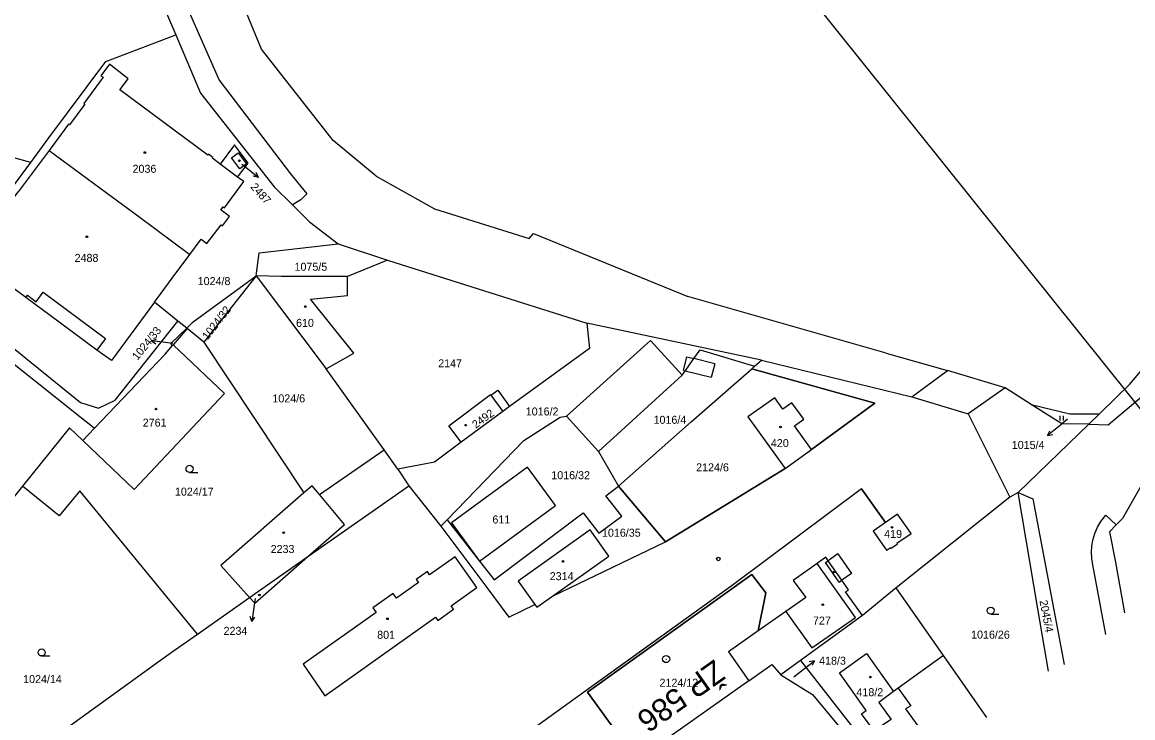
# Model space of a CAD drawing. Extents: x -793666 to -785424, y -1118958 to -1108761.
# Drawn here: x -792219.4 to -791983.5, y -1109753.4 to -1109605.6 of the extents above; entities that cross this region are included whole.
import ezdxf

# ---------------------------------------------------------------- set-up
doc = ezdxf.new("R2010")
doc.units = 0
for name, color, linetype in [('1', 7, 'Continuous'), ('1_2000 - úřady', 7, 'Continuous'), ('Hranice parcel', 7, 'Continuous'), ('Parcelní čísla', 7, 'Continuous'), ('Pop  PČ popisy', 7, 'Continuous'), ('Vnitřní kresba', 7, 'Continuous'), ('Vrstva 44', 7, 'Continuous'), ('Vrstva 53', 7, 'Continuous'), ('Vrstva 63', 7, 'Continuous'), ('Značky budov', 7, 'Continuous'), ('Značky kultur', 7, 'Continuous')]:
    doc.layers.add(name, color=color, linetype=linetype)

msp = doc.modelspace()

# ---------------------------------------------------------------- linework, layer by layer
at = {"layer": '1'}
for p, q in [((-792041.12, -1109704.75), (-792068.33, -1109725.02)), ((-792041.12, -1109704.75), (-792036.03, -1109711.9)), ((-792068.33, -1109725.02), (-792087.87, -1109739.13)), ((-792087.87, -1109739.13), (-792101.91, -1109749.26))]:
    msp.add_line(p, q, dxfattribs=at)
msp.add_lwpolyline([(-792036.03, -1109711.9), (-792041.12, -1109704.75), (-792068.33, -1109725.02), (-792101.91, -1109749.26), (-792182.09, -1109807.15)], dxfattribs=at)
msp.add_circle((-792071.53, -1109719.62), 0.375, dxfattribs=at)
at = {"layer": '1_2000 - úřady'}
msp.add_lwpolyline([(-791938.08, -1109742.36), (-792598.01, -1110271.46), (-792786.15, -1110036.8), (-792126.22, -1109507.7)], close=True, dxfattribs=at)
at = {"layer": 'Hranice parcel'}
for p, q in [((-792144.2, -1109638.25), (-792153.37, -1109630.69)), ((-792213.73, -1109632.8), (-792220.3, -1109641.62)), ((-792221.51, -1109640.65), (-792217.57, -1109635.36)), ((-792173.66, -1109638.47), (-792177.37, -1109635.72)), ((-792110.82, -1109650.45), (-792078.02, -1109663.86)), ((-792152.29, -1109652.69), (-792141.79, -1109656.16)), ((-792141.79, -1109656.16), (-792150.31, -1109659.57)), ((-792141.79, -1109656.16), (-792099.45, -1109669.52)), ((-792169.71, -1109659.46), (-792180.81, -1109673.54)), ((-792169.71, -1109659.46), (-792154.82, -1109679.25)), ((-792186.33, -1109669.08), (-792191.31, -1109665.06)), ((-792035.89, -1109675.87), (-792078.02, -1109663.86)), ((-792184.48, -1109670.58), (-792186.33, -1109669.08)), ((-792062.33, -1109677.36), (-792099.45, -1109669.52)), ((-792184.35, -1109670.68), (-792187.37, -1109674.13)), ((-792184.48, -1109670.58), (-792184.35, -1109670.68)), ((-792180.81, -1109673.54), (-792184.35, -1109670.68)), ((-792187.37, -1109674.13), (-792187.46, -1109674.24)), ((-792180.81, -1109673.54), (-792159.56, -1109705.6)), ((-792035.89, -1109675.87), (-792022.82, -1109679.59)), ((-792064.43, -1109679.2), (-792063.84, -1109678.68)), ((-792063.84, -1109678.68), (-792062.33, -1109677.36)), ((-792010.6, -1109683.28), (-792022.82, -1109679.59)), ((-792005.04, -1109686.79), (-792010.6, -1109683.28)), ((-791987, -1109685.32), (-791984.15, -1109682.54)), ((-791987, -1109685.32), (-791990.54, -1109688.77)), ((-792117.28, -1109688.25), (-792126.16, -1109694.83)), ((-791990.54, -1109688.77), (-791992.82, -1109691)), ((-792007.85, -1109705.47), (-791992.82, -1109691)), ((-792206.56, -1109694.48), (-792204.05, -1109691.84)), ((-791974.78, -1109691.82), (-791985.69, -1109711.05)), ((-792057.33, -1109700.37), (-792051.73, -1109696.36)), ((-792139.61, -1109700.53), (-792137.25, -1109704.07)), ((-792057.33, -1109700.37), (-792082.74, -1109715.97)), ((-792219.35, -1109704.16), (-792293.96, -1109796.98)), ((-792158.73, -1109719.12), (-792137.25, -1109704.07)), ((-792137.25, -1109704.07), (-792130.48, -1109712.65)), ((-792082.74, -1109715.97), (-792092.71, -1109704.13)), ((-792007.85, -1109705.47), (-792009.6, -1109706.46)), ((-792009.6, -1109706.46), (-792033.77, -1109725.73)), ((-792130.48, -1109712.65), (-792129.14, -1109711.27)), ((-791989.17, -1109710.28), (-791986.99, -1109712.39)), ((-791985.69, -1109711.05), (-791986.99, -1109712.39)), ((-792106.76, -1109727.49), (-792082.74, -1109715.97)), ((-792171.12, -1109727.8), (-792158.73, -1109719.12)), ((-791989.17, -1109735.63), (-791991.98, -1109720.83)), ((-792033.77, -1109725.73), (-792040.87, -1109731.66)), ((-792023.66, -1109740.13), (-792033.77, -1109725.73)), ((-792182.21, -1109735.57), (-792171.12, -1109727.8)), ((-792040.87, -1109731.66), (-792054.08, -1109741.21)), ((-792014.46, -1109753.3), (-792023.66, -1109740.13)), ((-792054.08, -1109741.21), (-792058.28, -1109744.24)), ((-792065.02, -1109745.49), (-792088.89, -1109762.3))]:
    msp.add_line(p, q, dxfattribs=at)
for points in [[(-792216.04, -1109494.77), (-792211.63, -1109526.92), (-792206.15, -1109541.38), (-792188.4, -1109593.25), (-792177.58, -1109617.9), (-792162.42, -1109637.81), (-792158.94, -1109642.01), (-792160.24, -1109643.3), (-792162, -1109644.38)], [(-792153.37, -1109630.69), (-792168.6, -1109611.32), (-792177.54, -1109589.6), (-792190.39, -1109550.74), (-792201.74, -1109515.1), (-792204.07, -1109507.78)], [(-792207.68, -1109547.79), (-792203.58, -1109560.85), (-792192.49, -1109594.88), (-792186.8, -1109608.25)], [(-792217.57, -1109635.36), (-792213.74, -1109630.12), (-792201.64, -1109613.93), (-792186.8, -1109608.25)], [(-792186.8, -1109608.25), (-792181.52, -1109620.67), (-792165.87, -1109640.54), (-792162, -1109644.38)], [(-792177.37, -1109635.72), (-792179.03, -1109634.49), (-792178.9, -1109634.32), (-792179.84, -1109633.63), (-792179.96, -1109633.8), (-792198.68, -1109619.95), (-792196.88, -1109617.57), (-792200.88, -1109614.49), (-792202.69, -1109616.98), (-792202.24, -1109617.28), (-792206.36, -1109622.83), (-792206.12, -1109623.01), (-792209.36, -1109627.39), (-792209.6, -1109627.21), (-792213.73, -1109632.8)], [(-792173.66, -1109638.47), (-792171.45, -1109635.49), (-792174.33, -1109631.62), (-792177.37, -1109635.72)], [(-791984.15, -1109682.54), (-791976.2, -1109673.16), (-791951.58, -1109631.36)], [(-792217.57, -1109635.36), (-792223.23, -1109633.79), (-792229.23, -1109634.41)], [(-792213.73, -1109632.8), (-792201.58, -1109641.77), (-792194.65, -1109646.88), (-792183.83, -1109654.9)], [(-792265.17, -1109639.25), (-792207.01, -1109686.37), (-792203.19, -1109687.6), (-792199.7, -1109685.86), (-792186.33, -1109669.08)], [(-792183.83, -1109654.9), (-792181.4, -1109651.65), (-792180.18, -1109652.56), (-792177.13, -1109648.66), (-792176.88, -1109648.85), (-792175.39, -1109646.84), (-792177.24, -1109645.47), (-792176.73, -1109644.79), (-792176.47, -1109644.98), (-792172.37, -1109639.42), (-792173.66, -1109638.47)], [(-792144.2, -1109638.25), (-792131.8, -1109645.19), (-792111.75, -1109651.55), (-792110.82, -1109650.45)], [(-792269.36, -1109639.81), (-792207.16, -1109689.36), (-792204.47, -1109691.5), (-792204.05, -1109691.84)], [(-792191.31, -1109665.06), (-792200.45, -1109677.48), (-792203.54, -1109675.23), (-792211.54, -1109669.29), (-792218.63, -1109664.04), (-792221.71, -1109661.79), (-792221.38, -1109661.32), (-792230.1, -1109654.77), (-792228.64, -1109652.81), (-792220.3, -1109641.62)], [(-792162, -1109644.38), (-792158.37, -1109647.98), (-792152.29, -1109652.69)], [(-792169.71, -1109659.46), (-792169.08, -1109654.55), (-792152.29, -1109652.69)], [(-792191.31, -1109665.06), (-792189.92, -1109663.17), (-792187.54, -1109659.95), (-792183.83, -1109654.9)], [(-792184.48, -1109670.58), (-792183.09, -1109669.26), (-792169.71, -1109659.46)], [(-792150.31, -1109659.57), (-792164.44, -1109659.59), (-792169.71, -1109659.46)], [(-792154.82, -1109679.25), (-792148.96, -1109675.87), (-792158.15, -1109664.45), (-792150.34, -1109663.66), (-792150.31, -1109659.57)], [(-792099.45, -1109669.52), (-792098.89, -1109674.87), (-792115.88, -1109687.23), (-792117.28, -1109688.25)], [(-792187.46, -1109674.24), (-792187.87, -1109673.81), (-792184.48, -1109670.58)], [(-792187.37, -1109674.13), (-792176.46, -1109684.49), (-792195.66, -1109704.89), (-792206.56, -1109694.48)], [(-792204.05, -1109691.84), (-792189.07, -1109676.08), (-792187.46, -1109674.24)], [(-792103.8, -1109689.27), (-792085.97, -1109673.17), (-792079.18, -1109680.58), (-792078.56, -1109679.69), (-792076.71, -1109677.05), (-792075.42, -1109675.2), (-792063.84, -1109678.68)], [(-792139.61, -1109700.53), (-792142.53, -1109696.46), (-792154.82, -1109679.25)], [(-792092.71, -1109704.13), (-792077.28, -1109690.45), (-792064.43, -1109679.2)], [(-792064.43, -1109679.2), (-792038.26, -1109686.52), (-792051.73, -1109696.36)], [(-792062.33, -1109677.36), (-792030.44, -1109685.15), (-792018.46, -1109688.78), (-792009.6, -1109706.46)], [(-792126.16, -1109694.83), (-792128.78, -1109691.3), (-792119.95, -1109684.65), (-792119.83, -1109684.81), (-792117.28, -1109688.25)], [(-792051.73, -1109696.36), (-792055.31, -1109691.31), (-792053.36, -1109689.93), (-792055.88, -1109686.41), (-792057.81, -1109687.78), (-792059.53, -1109685.37), (-792065.26, -1109689.44), (-792057.33, -1109700.37)], [(-791992.82, -1109691), (-791998.55, -1109690.88), (-792005.04, -1109686.79)], [(-792005.04, -1109686.79), (-791996.82, -1109688.79), (-791990.54, -1109688.77)], [(-792129.14, -1109711.27), (-792112.82, -1109694.46), (-792105.12, -1109689.46), (-792103.8, -1109689.27)], [(-792103.8, -1109689.27), (-792096.98, -1109696.76), (-792092.71, -1109704.13)], [(-792206.56, -1109694.48), (-792209.4, -1109691.78), (-792219.35, -1109704.16)], [(-792126.16, -1109694.83), (-792131.81, -1109699.06), (-792139.61, -1109700.53)], [(-792106.12, -1109708.23), (-792112.07, -1109700.09), (-792128.21, -1109711.96), (-792122.26, -1109720.08), (-792106.12, -1109708.23)], [(-792182.21, -1109735.57), (-792185.42, -1109731.65), (-792207.17, -1109705.16), (-792211.55, -1109710.42), (-792219.35, -1109704.16)], [(-792158.73, -1109719.12), (-792150.95, -1109712.28), (-792156.26, -1109705.94), (-792157.82, -1109704.08), (-792159.56, -1109705.6)], [(-792129.14, -1109711.27), (-792122.26, -1109720.08), (-792119.15, -1109724.06), (-792100.25, -1109709.81), (-792096.91, -1109714.15), (-792092.06, -1109710.49), (-792095.42, -1109706.17), (-792092.71, -1109704.13)], [(-792007.85, -1109705.47), (-792004.71, -1109706.83), (-791998.08, -1109742.02)], [(-792001.39, -1109743.48), (-792003.64, -1109730.21), (-792007.85, -1109705.47)], [(-792159.56, -1109705.6), (-792177.21, -1109720.99), (-792171.12, -1109727.8)], [(-792038.61, -1109713.71), (-792035.77, -1109717.77), (-792034.88, -1109717.16), (-792034.78, -1109717.31), (-792033.49, -1109716.43), (-792033.6, -1109716.27), (-792030.57, -1109714.17), (-792033.44, -1109710.08), (-792038.61, -1109713.71)], [(-791991.98, -1109720.83), (-791992.2, -1109719.5), (-791992.26, -1109718.2), (-791992.18, -1109716.87), (-791991.97, -1109715.65), (-791991.56, -1109714.23), (-791990.95, -1109712.85), (-791990.23, -1109711.63), (-791989.17, -1109710.28)], [(-791986.99, -1109712.39), (-791988.4, -1109713.84), (-791987.24, -1109719.97), (-791985.22, -1109731.09)], [(-792130.48, -1109712.65), (-792120.92, -1109725.39), (-792116.05, -1109731.95), (-792110.51, -1109729.29)], [(-792106.76, -1109727.49), (-792094.78, -1109719), (-792098.73, -1109713.45), (-792114.05, -1109724.35), (-792110.51, -1109729.29)], [(-792171.12, -1109727.8), (-792170.01, -1109729.04), (-792158.73, -1109719.12)], [(-792139.92, -1109727.96), (-792140.61, -1109726.97), (-792144.91, -1109730.01), (-792144.21, -1109731), (-792159.76, -1109741.99), (-792155.1, -1109748.67), (-792131.63, -1109731.96), (-792131.14, -1109732.66), (-792127.76, -1109730.25), (-792128.26, -1109729.56), (-792122.8, -1109725.68), (-792127.44, -1109719.13), (-792132.86, -1109722.97), (-792133.35, -1109722.27), (-792135.73, -1109723.95), (-792135.23, -1109724.65), (-792139.92, -1109727.96)], [(-792040.87, -1109731.66), (-792044.51, -1109726.58), (-792043.88, -1109726.16), (-792045.28, -1109724.14), (-792048.16, -1109719.98), (-792048.66, -1109719.25), (-792050.55, -1109720.58), (-792055.65, -1109724.16), (-792052.97, -1109727.83), (-792057.17, -1109730.8), (-792063.04, -1109734.91)], [(-792088.89, -1109762.3), (-792099.3, -1109747.92), (-792064.44, -1109722.94), (-792061.45, -1109726.78), (-792063.04, -1109734.91)], [(-792110.51, -1109729.29), (-792110.1, -1109729.86), (-792106.76, -1109727.49)], [(-792226.53, -1109766.83), (-792215.1, -1109759.26), (-792190.07, -1109741.13), (-792187.8, -1109739.49), (-792182.21, -1109735.57)], [(-792063.04, -1109734.91), (-792069.34, -1109739.32), (-792065.02, -1109745.49)], [(-792023.66, -1109740.13), (-792033.34, -1109747.1), (-792034.31, -1109747.79), (-792037.43, -1109750.08), (-792034.83, -1109753.69), (-792037.49, -1109755.5), (-792038.39, -1109756.14), (-792040.93, -1109758.03)], [(-792065.02, -1109745.49), (-792060.13, -1109742.03), (-792058.28, -1109744.24)], [(-792054.08, -1109741.21), (-792043.97, -1109754.14), (-792040.93, -1109758.03)], [(-792058.28, -1109744.24), (-792051.53, -1109748.38), (-792045.65, -1109755.46)]]:
    msp.add_lwpolyline(points, dxfattribs=at)
at = {"layer": 'Pop  PČ popisy'}
for p, q in [((-792172.78, -1109635.7), (-792171.57, -1109636.67)), ((-792171.57, -1109636.67), (-792169.24, -1109638.56)), ((-792169.24, -1109638.56), (-792170.33, -1109638.32)), ((-792169.24, -1109638.56), (-792169.7, -1109637.54)), ((-792191.93, -1109673.28), (-792190.87, -1109672.91)), ((-792188.95, -1109673.65), (-792191.93, -1109673.28)), ((-792191.93, -1109673.28), (-792191, -1109673.9)), ((-792187.42, -1109673.83), (-792188.95, -1109673.65)), ((-791997.32, -1109689.94), (-791999.25, -1109691.51)), ((-791999.25, -1109691.51), (-792001.58, -1109693.4)), ((-792001.58, -1109693.4), (-792001.12, -1109692.38)), ((-792001.58, -1109693.4), (-792000.49, -1109693.16)), ((-792169.95, -1109728.01), (-792170.22, -1109729.94)), ((-792170.22, -1109729.94), (-792170.64, -1109732.91)), ((-792170.64, -1109732.91), (-792170.99, -1109731.85)), ((-792170.64, -1109732.91), (-792170, -1109731.99)), ((-792055.48, -1109744.64), (-792053.48, -1109743.08)), ((-792053.48, -1109743.08), (-792051.11, -1109741.23)), ((-792051.11, -1109741.23), (-792052.21, -1109741.45)), ((-792051.11, -1109741.23), (-792051.6, -1109742.24))]:
    msp.add_line(p, q, dxfattribs=at)
at = {"layer": 'Vnitřní kresba'}
for p, q in [((-792174.94, -1109634.37), (-792173.55, -1109633.31)), ((-792173.16, -1109636.7), (-792174.94, -1109634.37)), ((-792173.55, -1109633.31), (-792171.76, -1109635.66)), ((-792171.76, -1109635.66), (-792173.16, -1109636.7)), ((-792216.48, -1109664.97), (-792214.98, -1109662.95)), ((-792214.98, -1109662.95), (-792201.7, -1109672.81)), ((-792218.63, -1109664.04), (-792218.32, -1109663.59)), ((-792218.32, -1109663.59), (-792216.48, -1109664.97)), ((-792201.7, -1109672.81), (-792203.54, -1109675.23)), ((-792078.96, -1109679.59), (-792078.25, -1109676.66)), ((-792078.25, -1109676.66), (-792076.71, -1109677.05)), ((-792072.3, -1109678.15), (-792076.71, -1109677.05)), ((-792072.3, -1109678.15), (-792073.02, -1109681.03)), ((-792079.18, -1109680.58), (-792096.98, -1109696.76)), ((-792078.96, -1109679.59), (-792078.56, -1109679.69)), ((-792073.02, -1109681.03), (-792078.56, -1109679.69)), ((-792030.44, -1109685.15), (-792022.82, -1109679.59)), ((-792119.83, -1109684.81), (-792118.4, -1109683.76)), ((-792118.4, -1109683.76), (-792115.88, -1109687.23)), ((-792010.6, -1109683.28), (-792018.46, -1109688.78)), ((-791988.67, -1109691.09), (-791981.02, -1109684.68)), ((-791992.82, -1109691), (-791988.67, -1109691.09)), ((-792156.26, -1109705.94), (-792142.53, -1109696.46)), ((-792046.11, -1109718.56), (-792048.16, -1109719.98)), ((-792046.11, -1109718.56), (-792043.21, -1109722.69)), ((-792042.35, -1109732.05), (-792050.55, -1109720.58)), ((-792048.75, -1109720.39), (-792048.16, -1109719.98)), ((-792045.84, -1109724.54), (-792048.75, -1109720.39)), ((-792045.84, -1109724.54), (-792045.28, -1109724.14)), ((-792043.21, -1109722.69), (-792045.28, -1109724.14)), ((-792057.17, -1109730.8), (-792051.69, -1109738.52)), ((-792051.69, -1109738.52), (-792042.35, -1109732.05)), ((-792045.81, -1109743.8), (-792040.07, -1109739.73)), ((-792040.07, -1109739.73), (-792034.31, -1109747.79)), ((-792040.1, -1109751.84), (-792045.81, -1109743.8)), ((-792033.34, -1109747.1), (-792030.63, -1109750.85)), ((-792041.08, -1109752.55), (-792040.1, -1109751.84)), ((-792038.39, -1109756.14), (-792041.08, -1109752.55)), ((-792030.63, -1109750.85), (-792031.74, -1109751.44)), ((-792031.74, -1109751.44), (-792025.88, -1109759.58))]:
    msp.add_line(p, q, dxfattribs=at)
at = {"layer": 'Vrstva 44'}
msp.add_line((-792064.2, -1109679.26), (-792064.2, -1109679), dxfattribs=at)
at = {"layer": 'Vrstva 53'}
for points in [[(-792038.26, -1109686.52), (-792064.43, -1109679.2), (-792062.33, -1109677.36), (-792030.44, -1109685.15), (-792018.46, -1109688.78), (-792009.6, -1109706.46)], [(-792226.53, -1109766.83), (-792215.1, -1109759.26), (-792190.07, -1109741.13), (-792187.8, -1109739.49), (-792182.21, -1109735.57), (-792171.12, -1109727.8), (-792158.73, -1109719.12), (-792137.25, -1109704.07), (-792130.48, -1109712.65), (-792129.14, -1109711.27), (-792119.15, -1109724.06), (-792100.25, -1109709.81), (-792096.91, -1109714.15), (-792092.06, -1109710.49), (-792095.42, -1109706.17), (-792092.71, -1109704.13), (-792082.74, -1109715.97), (-792057.33, -1109700.37), (-792051.73, -1109696.36), (-792038.26, -1109686.52)], [(-792009.6, -1109706.46), (-792033.77, -1109725.73), (-792040.87, -1109731.66), (-792044.51, -1109726.58), (-792043.88, -1109726.16), (-792045.28, -1109724.14), (-792048.16, -1109719.98), (-792048.66, -1109719.25), (-792050.55, -1109720.58), (-792055.65, -1109724.16), (-792052.97, -1109727.83), (-792057.17, -1109730.8), (-792063.04, -1109734.91), (-792061.45, -1109726.78), (-792064.44, -1109722.94), (-792099.3, -1109747.92), (-792088.89, -1109762.3)]]:
    msp.add_lwpolyline(points, dxfattribs=at)
at = {"layer": 'Vrstva 63'}
msp.add_line((-792082.67, -1109740.89), (-792082.57, -1109740.89), dxfattribs=at)
msp.add_circle((-792082.62, -1109740.89), 0.756, dxfattribs=at)
at = {"layer": 'Značky budov'}
for centre in [(-792193.36, -1109633.26), (-792173.31, -1109635.02), (-792205.68, -1109651.17), (-792159.28, -1109665.98), (-792190.99, -1109687.76), (-792125.19, -1109691.19), (-792058.33, -1109691.59), (-792163.87, -1109714.03), (-792034.61, -1109712.91), (-792104.52, -1109720.15), (-792046.93, -1109722.38), (-792169.02, -1109727.27), (-792049.34, -1109729.33), (-792141.82, -1109732.33), (-792039.24, -1109744.72)]:
    msp.add_circle(centre, 0.175, dxfattribs=at)
at = {"layer": 'Značky kultur'}
for p, q in [((-791998.9, -1109690.22), (-791998.9, -1109689.17)), ((-791998.2, -1109690.22), (-791998.2, -1109689.17)), ((-792183.87, -1109701.22), (-792182.12, -1109701.22)), ((-792013.65, -1109731.34), (-792011.9, -1109731.34)), ((-792215.3, -1109740.23), (-792213.55, -1109740.23))]:
    msp.add_line(p, q, dxfattribs=at)
for centre in [(-792183.87, -1109700.47), (-792013.65, -1109730.59), (-792215.3, -1109739.48)]:
    msp.add_circle(centre, 0.75, dxfattribs=at)

# ---------------------------------------------------------------- texts
at = {"layer": 'Parcelní čísla'}
for s, p in [('2036', (-792195.98, -1109637.57)), ('2488', (-792208.29, -1109656.5)), ('1075/5', (-792161.57, -1109658.38)), ('1024/8', (-792182.14, -1109661.43)), ('610', (-792161.24, -1109670.3)), ('2147', (-792131.04, -1109678.9)), ('1024/6', (-792166.27, -1109686.35)), ('1016/2', (-792112.44, -1109689.13)), ('2761', (-792193.82, -1109691.5)), ('1016/4', (-792085.29, -1109690.9)), ('420', (-792060.36, -1109695.85)), ('1015/4', (-792009.18, -1109696.24)), ('2124/6', (-792076.24, -1109701)), ('1016/32', (-792107.01, -1109702.67)), ('1024/17', (-792186.97, -1109706.16)), ('611', (-792119.52, -1109712.08)), ('1016/35', (-792096.24, -1109714.89)), ('419', (-792036.29, -1109715.14)), ('2233', (-792166.64, -1109718.35)), ('2314', (-792107.35, -1109724.12)), ('727', (-792051.42, -1109733.56)), ('2234', (-792176.64, -1109735.74)), ('801', (-792144.01, -1109736.58)), ('1016/26', (-792017.82, -1109736.55)), ('418/3', (-792050.11, -1109742.08)), ('1024/14', (-792219.23, -1109745.98)), ('2124/12', (-792084.02, -1109746.76)), ('418/2', (-792042.18, -1109748.77))]:
    msp.add_text(s, height=1.7, dxfattribs=at).set_placement(p)
for s, rotation, p in [('2487', 312, (-792171.04, -1109640.65)), ('1024/32', 52, (-792180.04, -1109673.18)), ('1024/33', 51, (-792194.92, -1109677.51)), ('2492', 36, (-792123.08, -1109691.99)), ('2045/4', 281, (-792003.3, -1109728.51))]:
    msp.add_text(s, height=1.7, rotation=rotation, dxfattribs=at).set_placement(p)
at = {"layer": 'Vrstva 63'}
msp.add_text('ŽP 586', height=4.8, rotation=215.3692, dxfattribs=at).set_placement((-792072.35, -1109740.83))

doc.saveas('drawing.dxf')
